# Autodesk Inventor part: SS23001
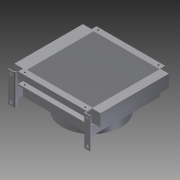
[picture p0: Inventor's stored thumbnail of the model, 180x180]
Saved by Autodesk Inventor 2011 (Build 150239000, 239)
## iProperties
Created: 2011-07
Part Number: SS23001
Document SubType Name: Modeling
Designer: khramov
Density: 1 g/cm^3
Mass: 21640.7 g
Surface Area: 6708.49 cm^2
Volume: 21640.7 cm^3
Author: khramov
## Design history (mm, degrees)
sketch "Эскиз1"
  geometry: L1 (-25.268, 18.989)-(412.732, 18.989); L2 (412.732, 18.989)-(412.732, -380.011); L3 (412.732, -380.011)-(-25.268, -380.011); L4 (-25.268, -380.011)-(-25.268, 18.989); 1 further point
  constraints: 8 end point, 2 parallel, 1 horizontal, 1 perpendicular
  dimensions: "d0" = 438 distance of L1.start L1.end; "d1" = 399 distance of L3.end L1.start
extrude "Выдавливание1" new body sketch "Эскиз1" distance "d2" = 63; taper "d3" = 0 deg
sketch "Эскиз2"
  geometry: L1 (25.268, 18.989)-(-412.732, 18.989) reference; L2 (-412.732, 18.989)-(-412.732, -380.011) reference; L3 (-412.732, -380.011)-(25.268, -380.011) reference; L4 (25.268, -380.011)-(25.268, 18.989) reference; L5 (-368.732, -6.011)-(-18.732, -6.011); L6 (-18.732, -6.011)-(-18.732, -355.011); L7 (-18.732, -355.011)-(-368.732, -355.011); L8 (-368.732, -355.011)-(-368.732, -6.011); L9 (-193.732, 18.989)-(-193.732, -380.011); L10 (-412.732, -180.511)-(25.268, -180.511); 1 further point
  constraints: 12 end point, 4 midpoint, 2 parallel, 1 horizontal, 1 perpendicular
  dimensions: "d4" = 350 distance of L5.start L5.end; "d5" = 175 distance between parallel lines of L9 L8; "d6" = 349 distance of L7.end L5.start; "d7" = 174.5 distance between parallel lines of L7 L10
extrude "Выдавливание2" join sketch "Эскиз2" distance "d8" = 60; taper "d9" = 0 deg
sketch "Эскиз3"
  geometry: L1 (-368.732, -6.011)-(-18.732, -355.011); L2 (-18.732, -6.011)-(-368.732, -355.011); C1 r 150 at (-193.732, -180.511); 1 further point
  constraints: 4 end point, 1 centre point, 1 midpoint
  dimensions: "d10" = 300 diameter of C1
extrude "Выдавливание3" join sketch "Эскиз3" distance "d11" = 60; taper "d12" = 0 deg
sketch "Эскиз4"
  geometry: L1 (-63, 399)-(-63, 0) reference; L2 (0, 399)-(0, 0) reference; L3 (0, 399)-(-63, 399) reference; L4 (-55, 399)-(-8, 399); L5 (-8, 399)-(-8, 374); L6 (-8, 374)-(-55, 374); L7 (-55, 374)-(-55, 399); L8 (-63, 0)-(-63, 399) reference; L9 (-63, 199.5)-(201.133, 199.5); L10 (-55, 0)-(-8, 0); L11 (-8, 0)-(-8, 25); L12 (-8, 25)-(-55, 25); L13 (-55, 25)-(-55, 0); 1 further point
  constraints: 18 end point, 4 symmetric about line, 2 parallel, 2 perpendicular, 1 horizontal, 1 midpoint, 1 point on line
  dimensions: "d13" = 25 distance of L6.end L4.start; "d14" = 8 distance between parallel lines of L7 L1; "d15" = 8 distance between parallel lines of L2 L5
extrude "Выдавливание4" cut sketch "Эскиз4" stored distance "d16" = 60; taper "d17" = 0 deg
sketch "Эскиз5"
  geometry: L1 (-412.732, 18.989)-(-368.732, 18.989); L2 (-368.732, 18.989)-(-368.732, -6.011); L3 (-368.732, -6.011)-(-412.732, -6.011); L4 (-412.732, -6.011)-(-412.732, 18.989); L5 (25.268, 18.989)-(-18.732, 18.989); L6 (-18.732, 18.989)-(-18.732, -6.011); L7 (-18.732, -6.011)-(25.268, -6.011); L8 (25.268, -6.011)-(25.268, 18.989); L9 (25.268, -380.011)-(-18.732, -380.011); L10 (-18.732, -380.011)-(-18.732, -355.011); L11 (-18.732, -355.011)-(25.268, -355.011); L12 (25.268, -355.011)-(25.268, -380.011); L13 (-368.732, -355.011)-(-412.732, -355.011); L14 (-412.732, -355.011)-(-412.732, -380.011); L15 (-412.732, -380.011)-(-368.732, -380.011); L16 (-368.732, -380.011)-(-368.732, -355.011); 1 further point
  constraints: 32 end point, 8 parallel, 4 horizontal, 4 perpendicular
extrude "Выдавливание5" cut sketch "Эскиз5" stored distance "d18" = 60; taper "d19" = 0 deg
sketch "Эскиз7"
  geometry: L1 (-412.732, -355.011)-(-368.732, -355.011) reference; L2 (-368.732, -355.011)-(-368.732, -6.011) reference; L3 (-373.732, -355.011)-(-373.732, -393.011); L4 (-373.732, -393.011)-(-403.732, -393.011); L5 (-368.732, -380.011)-(-368.732, -355.011) reference; L6 (-388.732, -393.011)-(-388.732, -425.954); L7 (-18.732, -380.011)-(-368.732, -380.011) reference; L8 (-193.732, -380.011)-(-193.732, -627.687); L9 (-403.732, -393.011)-(-403.732, -397.011); L10 (-403.732, -397.011)-(-374.732, -397.011); L11 (-369.732, -392.011)-(-369.732, -355.011); L12 (-18.732, -355.011)-(-368.732, -355.011) reference; L13 (-13.732, -355.011)-(-13.732, -393.011); L14 (-17.732, -392.011)-(-17.732, -355.011); L15 (-13.732, -393.011)-(16.268, -393.011); L16 (16.268, -393.011)-(16.268, -397.011); L17 (16.268, -397.011)-(-12.732, -397.011); L18 (-373.732, -355.011)-(-369.732, -355.011); L19 (-17.732, -355.011)-(-13.732, -355.011); L20 (25.268, -355.011)-(-18.732, -355.011) reference; L21 (1.268, -393.011)-(1.268, -425.954); A1 r 5 centre (-374.732, -392.011) between (-374.732, -397.011) and (-369.732, -392.011); A2 r 5 centre (-12.732, -392.011) between (-17.732, -392.011) and (-12.732, -397.011); 7 further points
  constraints: 30 end point, 10 symmetric about line, 8 point on line, 4 perpendicular, 4 point on circle, 4 tangent, 2 centre point, 2 collinear, 2 midpoint, 2 parallel, 1 horizontal, 1 vertical, 8 other
  dimensions: "d28" = 4 distance of L4.end L9.end; "d29" = 4 distance between parallel lines of L3 L11; "d83" = 5 radius of A2; "d84" = 15 distance between parallel lines of L6 L9; "d88" = 42 distance between parallel lines of L10 L12; "d91" = 390 distance between parallel lines of L21 L6; "d92" = 15 distance between parallel lines of L6 L3
extrude "Выдавливание6" join sketch "Эскиз7" distance "d32" = 90; taper "d34" = 0 deg; dims "d33" = 66, "d35" = 0
sketch "Эскиз8"
  geometry: L1 (34, 156)-(34, 0) reference; L2 (19, 143)-(19, 17); L3 (43, 153)-(-1, 153) reference; L4 (19, 17)-(-371, 17); L5 (-371, 17)-(-371, 143); L6 (-371, 143)-(19, 143); L7 (-1, 153)-(-351, 153) reference; L8 (-176, 153)-(-176, 196.362); C1 r 6.5 at (-371, 143); C2 r 6.5 at (-371, 17); C3 r 6.5 at (19, 143); C4 r 6.5 at (19, 17)
  constraints: 10 end point, 4 centre point, 4 coincident, 3 perpendicular, 1 midpoint, 1 vertical
  dimensions: "d36" = 13 diameter of C4; "d37" = 13 diameter of C3; "d38" = 13 diameter of C1; "d39" = 13 diameter of C2; "d40" = 126 distance of L4.end L5.end; "d41" = 390 distance of L5.end L2.start; "d42" = 195 distance between parallel lines of L8 L5; "d94" = 10 distance between parallel lines of L6 L7
extrude "Выдавливание7" cut sketch "Эскиз8" distance "d46" = 10; taper "d47" = 0 deg
sketch "Эскиз10"
  geometry: L1 (368.732, -380.011)-(18.732, -380.011) reference; L2 (412.732, -6.011)-(412.732, -355.011) reference; L3 (39.732, 6.489)-(347.732, 6.489); L4 (347.732, 6.489)-(347.732, -367.511); L5 (347.732, -367.511)-(39.732, -367.511); L6 (39.732, -367.511)-(39.732, 6.489); L7 (18.732, 18.989)-(368.732, 18.989) reference; L8 (193.732, 18.989)-(193.732, -380.011); L9 (412.732, -180.511)-(-25.268, -180.511); L10 (-25.268, -355.011)-(-25.268, -6.011) reference; 5 further points
  constraints: 12 end point, 4 coincident, 4 midpoint, 2 parallel, 1 perpendicular
  dimensions: "d57" = 308 distance of L3.start L3.end; "d58" = 154 distance between parallel lines of L8 L6; "d59" = 374 distance of L3.end L4.end; "d60" = 187 distance between parallel lines of L3 L9
hole "Отверстие2" sketch "Эскиз10" at (39.732, 6.489), (347.732, 6.489), (347.732, -367.511), (39.732, -367.511) diameter "d61" = 9; stored, may be unused: countersink angle "d65" = 90 deg, drill point angle "d67" = 118 deg; dims "d62" = 20, "d63" = 4, "d64" = 2, "d66" = 70
sketch "Эскиз11"
  geometry: L1 (368.732, -380.011)-(18.732, -380.011) reference; L2 (18.732, 18.989)-(368.732, 18.989) reference; L3 (-25.268, -355.011)-(-25.268, -6.011) reference; L4 (368.732, -355.011)-(368.732, -6.011) reference; L5 (34.732, -350.011)-(368.732, -350.011); L6 (368.732, -350.011)-(368.732, -11.011); L7 (368.732, -11.011)-(34.732, -11.011); L8 (34.732, -11.011)-(34.732, -350.011); 1 further point
  constraints: 8 end point, 2 parallel, 1 horizontal, 1 perpendicular, 1 point on line
  dimensions: "d68" = 30 distance between parallel lines of L1 L5; "d69" = 30 distance between parallel lines of L7 L2; "d70" = 60 distance between parallel lines of L8 L3
extrude "Выдавливание8" join sketch "Эскиз11" distance "d71" = 1; taper "d72" = 0 deg
sketch "Эскиз12"
  geometry: L1 (63, 349)-(0, 349) reference; L2 (31.5, 349)-(31.5, 0); L3 (63, 0)-(0, 0) reference; L4 (66, -42)-(-90, -42) reference; 3 further points
  constraints: 2 end point, 2 midpoint, 2 point on line
  dimensions: "d73" = 279 distance of point (31.5, 36.5) point (31.5, 315.5); "d74" = 78.5 distance from line of point (31.5, 36.5) L4
hole "Отверстие3" sketch "Эскиз12" at (31.5, 315.5), (31.5, 36.5) diameter "d75" = 30.291; stored, may be unused: countersink angle "d79" = 90 deg, drill point angle "d81" = 118 deg; dims "d76" = 25, "d77" = 34, "d78" = 2, "d80" = 30
sketch "Эскиз13"
  geometry: L1 (-156, 11.597)-(-83.172, 20.133); L2 (-83.172, 20.133)-(-83.172, 42); L3 (-156, 42)-(-156, 11.597); L4 (-90, 42)-(-153, 42) reference; L5 (-156, 42)-(-83.172, 42); L6 (-34.199, 42)-(-34.199, 20.133); L7 (-34.199, 20.133)-(0, 11.597); L8 (0, 42)-(0, 11.597); L9 (-34.199, 42)-(0, 42); 1 further point
  constraints: 16 end point, 4 perpendicular
extrude "Выдавливание9" cut sketch "Эскиз13" stored distance "d95" = 0; taper "d96" = 0 deg
sketch "Эскиз14"
  geometry: L1 (-83.172, 15.133)-(-83.172, 37); L2 (-83.172, 15.133)-(-83.172, 37) reference; L3 (-83.172, 37)-(-156, 37); L4 (0, 37)-(0, 6.597); L5 (0, 6.597)-(-34.199, 15.133); L6 (-34.199, 15.133)-(0, 6.597) reference; L7 (-34.199, 15.133)-(-34.199, 37); L8 (-34.199, 37)-(0, 37); L9 (-83.172, 15.133)-(-156, 6.597); L10 (-156, 37)-(-156, 6.597); L11 (-156, 37)-(-156, 0) reference; 1 further point
  constraints: 16 end point, 3 collinear
extrude "Выдавливание10" cut sketch "Эскиз14" distance "d97" = 10; taper "d98" = 0 deg
sketch "Эскиз15"
  geometry: L1 (0, 21.867)-(4, 21.867) reference; L2 (4, 21.867)-(4, 23.857); L3 (1, 26.857)-(-1, 26.857); L4 (-1, 26.857)-(-1, 21.867); L5 (-1, 21.867)-(0, 21.867); L6 (4, 21.867)-(0, 21.867); L7 (-17, 365.867)-(-351, 365.867) reference; L8 (-351, -3.133)-(-1, -3.133) reference; L9 (-176, -3.133)-(-176, -127.553); L10 (-352, 21.867)-(-356, 21.867); L11 (-356, 21.867)-(-356, 23.857); L12 (-353, 26.857)-(-351, 26.857); L13 (-351, 26.857)-(-351, 21.867); L14 (-351, 21.867)-(-352, 21.867); L15 (-356, 21.867)-(-352, 21.867); A1 r 3 centre (1, 23.857) between (4, 23.857) and (1, 26.857); A2 r 3 centre (-353, 23.857) between (-353, 26.857) and (-356, 23.857); 1 further point
  constraints: 24 end point, 7 symmetric about line, 4 point on circle, 2 centre point, 2 perpendicular, 2 tangent, 1 collinear, 1 midpoint, 1 other
  dimensions: "d99" = 3 radius of A1
extrude "Выдавливание11" join sketch "Эскиз15" stored distance "d100" = 10; taper "d101" = 0 deg
node "Твердое тело1"
